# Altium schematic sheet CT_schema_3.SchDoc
size 362 x 192 mm
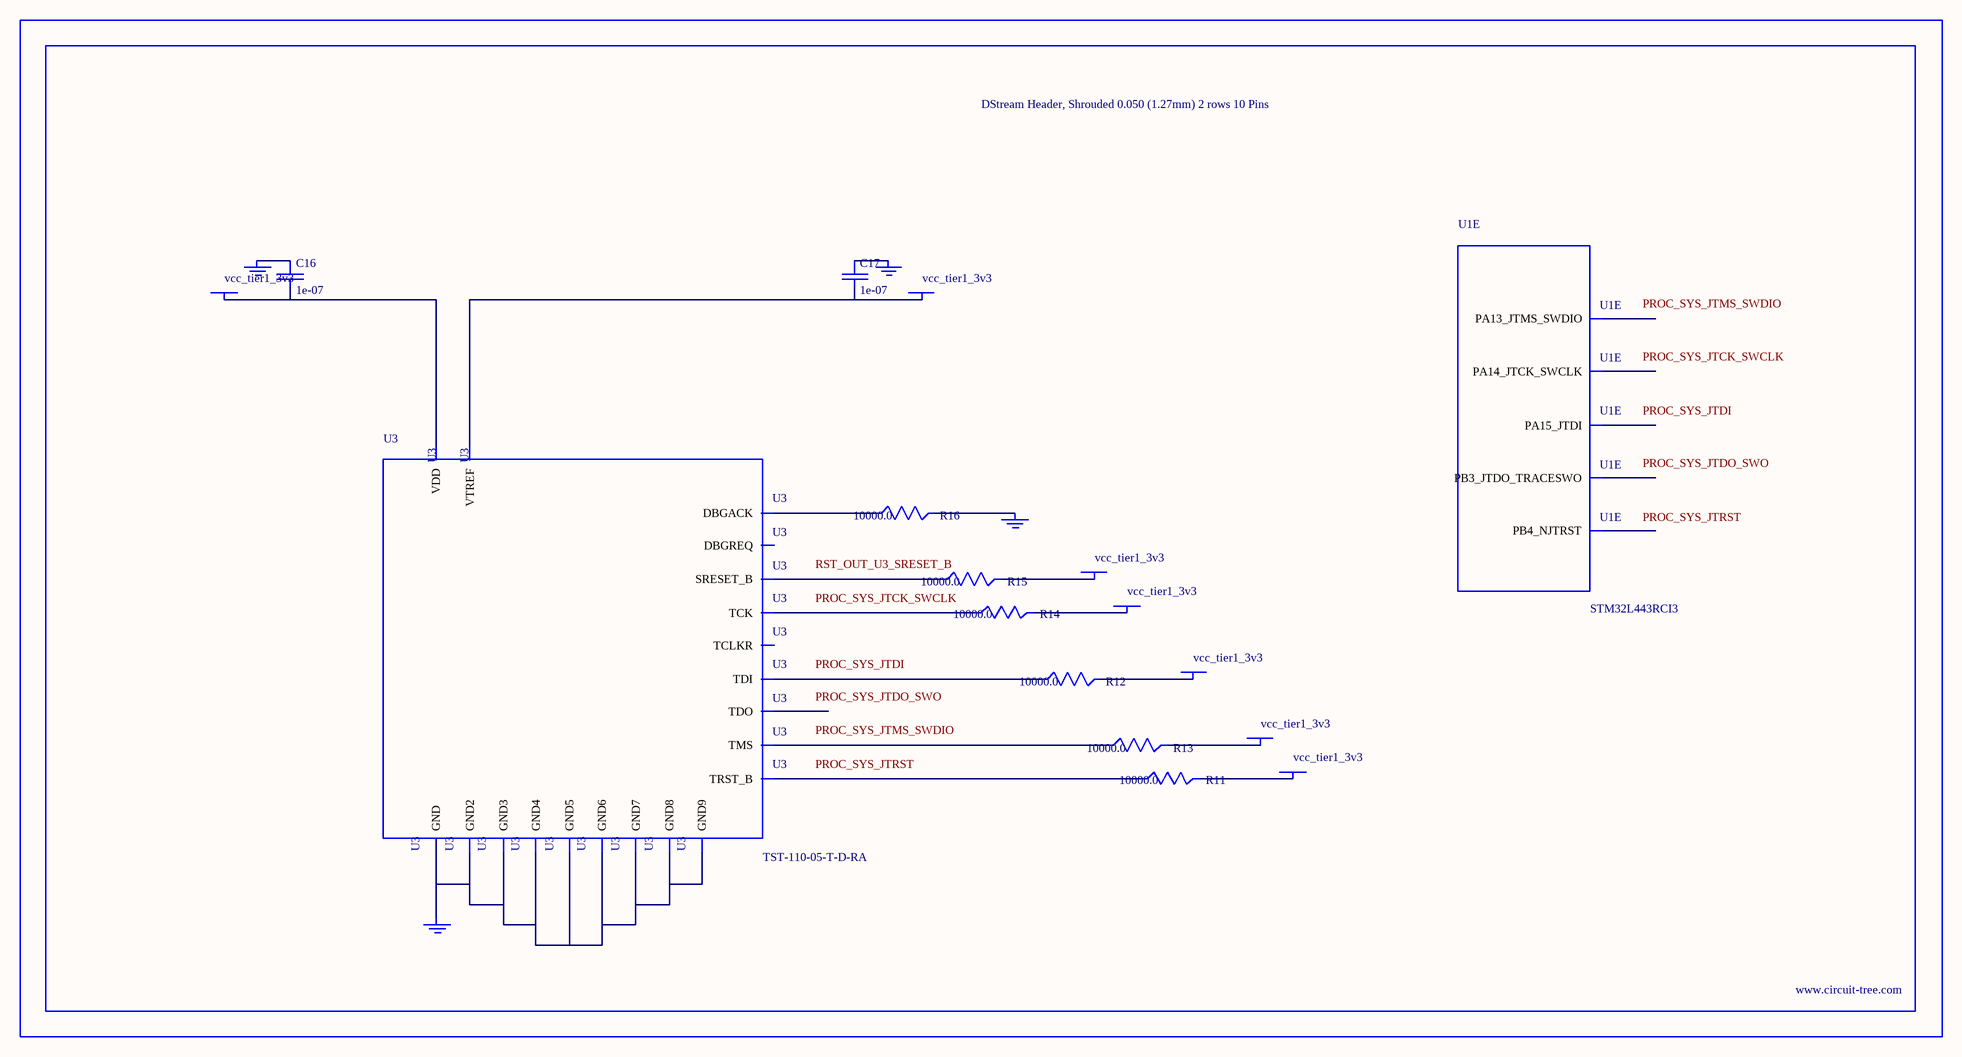
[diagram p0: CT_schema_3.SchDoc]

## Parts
BORDER2  (no value)
C16  1e-07  [C0402]
C17  1e-07  [C0402]
GND_INSTANCE_2_0  (no value)
GND_INSTANCE_2_1  (no value)
GND_INSTANCE_2_2  (no value)
GND_INSTANCE_2_3  (no value)
POWER_INSTANCE_2_0  vcc_tier1_3v3
POWER_INSTANCE_2_1  vcc_tier1_3v3
POWER_INSTANCE_2_2  vcc_tier1_3v3
POWER_INSTANCE_2_3  vcc_tier1_3v3
POWER_INSTANCE_2_4  vcc_tier1_3v3
POWER_INSTANCE_2_5  vcc_tier1_3v3
POWER_INSTANCE_2_6  vcc_tier1_3v3
R11  10000.0  [R0603]
R12  10000.0  [R0603]
R13  10000.0  [R0603]
R14  10000.0  [R0603]
R15  10000.0  [R0603]
R16  10000.0  [R0603]
U1  STM32L443RCI3  [UFBGA64]  (part E of 8)
U3  TST-110-05-T-D-RA  [TST-110-05-T-D-RA]

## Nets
NetC16_1: C16.1 GND_INSTANCE_2_1.0(GND)
NetC16_2: C16.2 POWER_INSTANCE_2_1.0(PWR) U3.2(VDD)
NetC17_1: C17.1 GND_INSTANCE_2_0.0(GND)
NetC17_2: C17.2 POWER_INSTANCE_2_0.0(PWR) U3.1(VTREF)
NetGND_INSTANCE_2_2_0: GND_INSTANCE_2_2.0(GND) R16.2
NetGND_INSTANCE_2_3_0: GND_INSTANCE_2_3.0(GND) U3.4(GND) U3.6(GND2) U3.8(GND3) U3.10(GND4) U3.12(GND5) U3.14(GND6) U3.16(GND7) U3.18(GND8) U3.20(GND9)
NetPOWER_INSTANCE_2_2_0: POWER_INSTANCE_2_2.0(PWR) R11.2
NetPOWER_INSTANCE_2_3_0: POWER_INSTANCE_2_3.0(PWR) R12.2
NetPOWER_INSTANCE_2_4_0: POWER_INSTANCE_2_4.0(PWR) R13.2
NetPOWER_INSTANCE_2_5_0: POWER_INSTANCE_2_5.0(PWR) R14.2
NetPOWER_INSTANCE_2_6_0: POWER_INSTANCE_2_6.0(PWR) R15.2
NetR11_1: R11.1 U3.3(TRST_B)
NetR12_1: R12.1 U3.5(TDI)
NetR13_1: R13.1 U3.7(TMS)
NetR14_1: R14.1 U3.9(TCK)
NetR15_1: R15.1 U3.15(SRESET_B)
NetR16_1: R16.1 U3.19(DBGACK)

Not connected (* = marked no-connect by the designer): U1 A4(PB4_NJTRST) A5(PB3_JTDO_TRACESWO) A6(PA15_JTDI) A7(PA14_JTCK_SWCLK) A8(PA13_JTMS_SWDIO); U3 11(TCLKR) 13(TDO) 17(DBGREQ)

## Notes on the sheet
- Labels drawn without touching a wire or pin: PROC_SYS_JTCK_SWCLK, PROC_SYS_JTDI, PROC_SYS_JTDO_SWO, PROC_SYS_JTMS_SWDIO, PROC_SYS_JTRST, RST_OUT_U3_SRESET_B

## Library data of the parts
BORDER2 = BORDER_PAGE2
C16 C17 = C0402C104K3RACTU
GND_INSTANCE_2_0-GND_INSTANCE_2_3 = GND
POWER_INSTANCE_2_0-POWER_INSTANCE_2_6 = PWR
R11-R16 = RC0603JR-0710KL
